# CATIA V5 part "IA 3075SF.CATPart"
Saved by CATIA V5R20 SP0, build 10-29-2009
Part number: IA 3075SF
Revision: ANY
Definition: UNKNOWN
Nomenclature: IA 3075SF
Source: Unknown
Bounding box of the stored display mesh (mm): x -1.5 to 1.5, y -2.85 to 4.9, z -1.5 to 1.5
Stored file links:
  C:\Users\Utente\Desktop\IO LAVORO\3D X SITO CF\CUMSA\3D files IA\IA 3075SF\IA 3075SF.CATPart
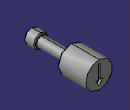
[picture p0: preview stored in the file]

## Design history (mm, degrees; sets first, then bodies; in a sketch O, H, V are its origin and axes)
Body1 "Cortar-Extruir1" (main body)
  Solid1: solid without history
